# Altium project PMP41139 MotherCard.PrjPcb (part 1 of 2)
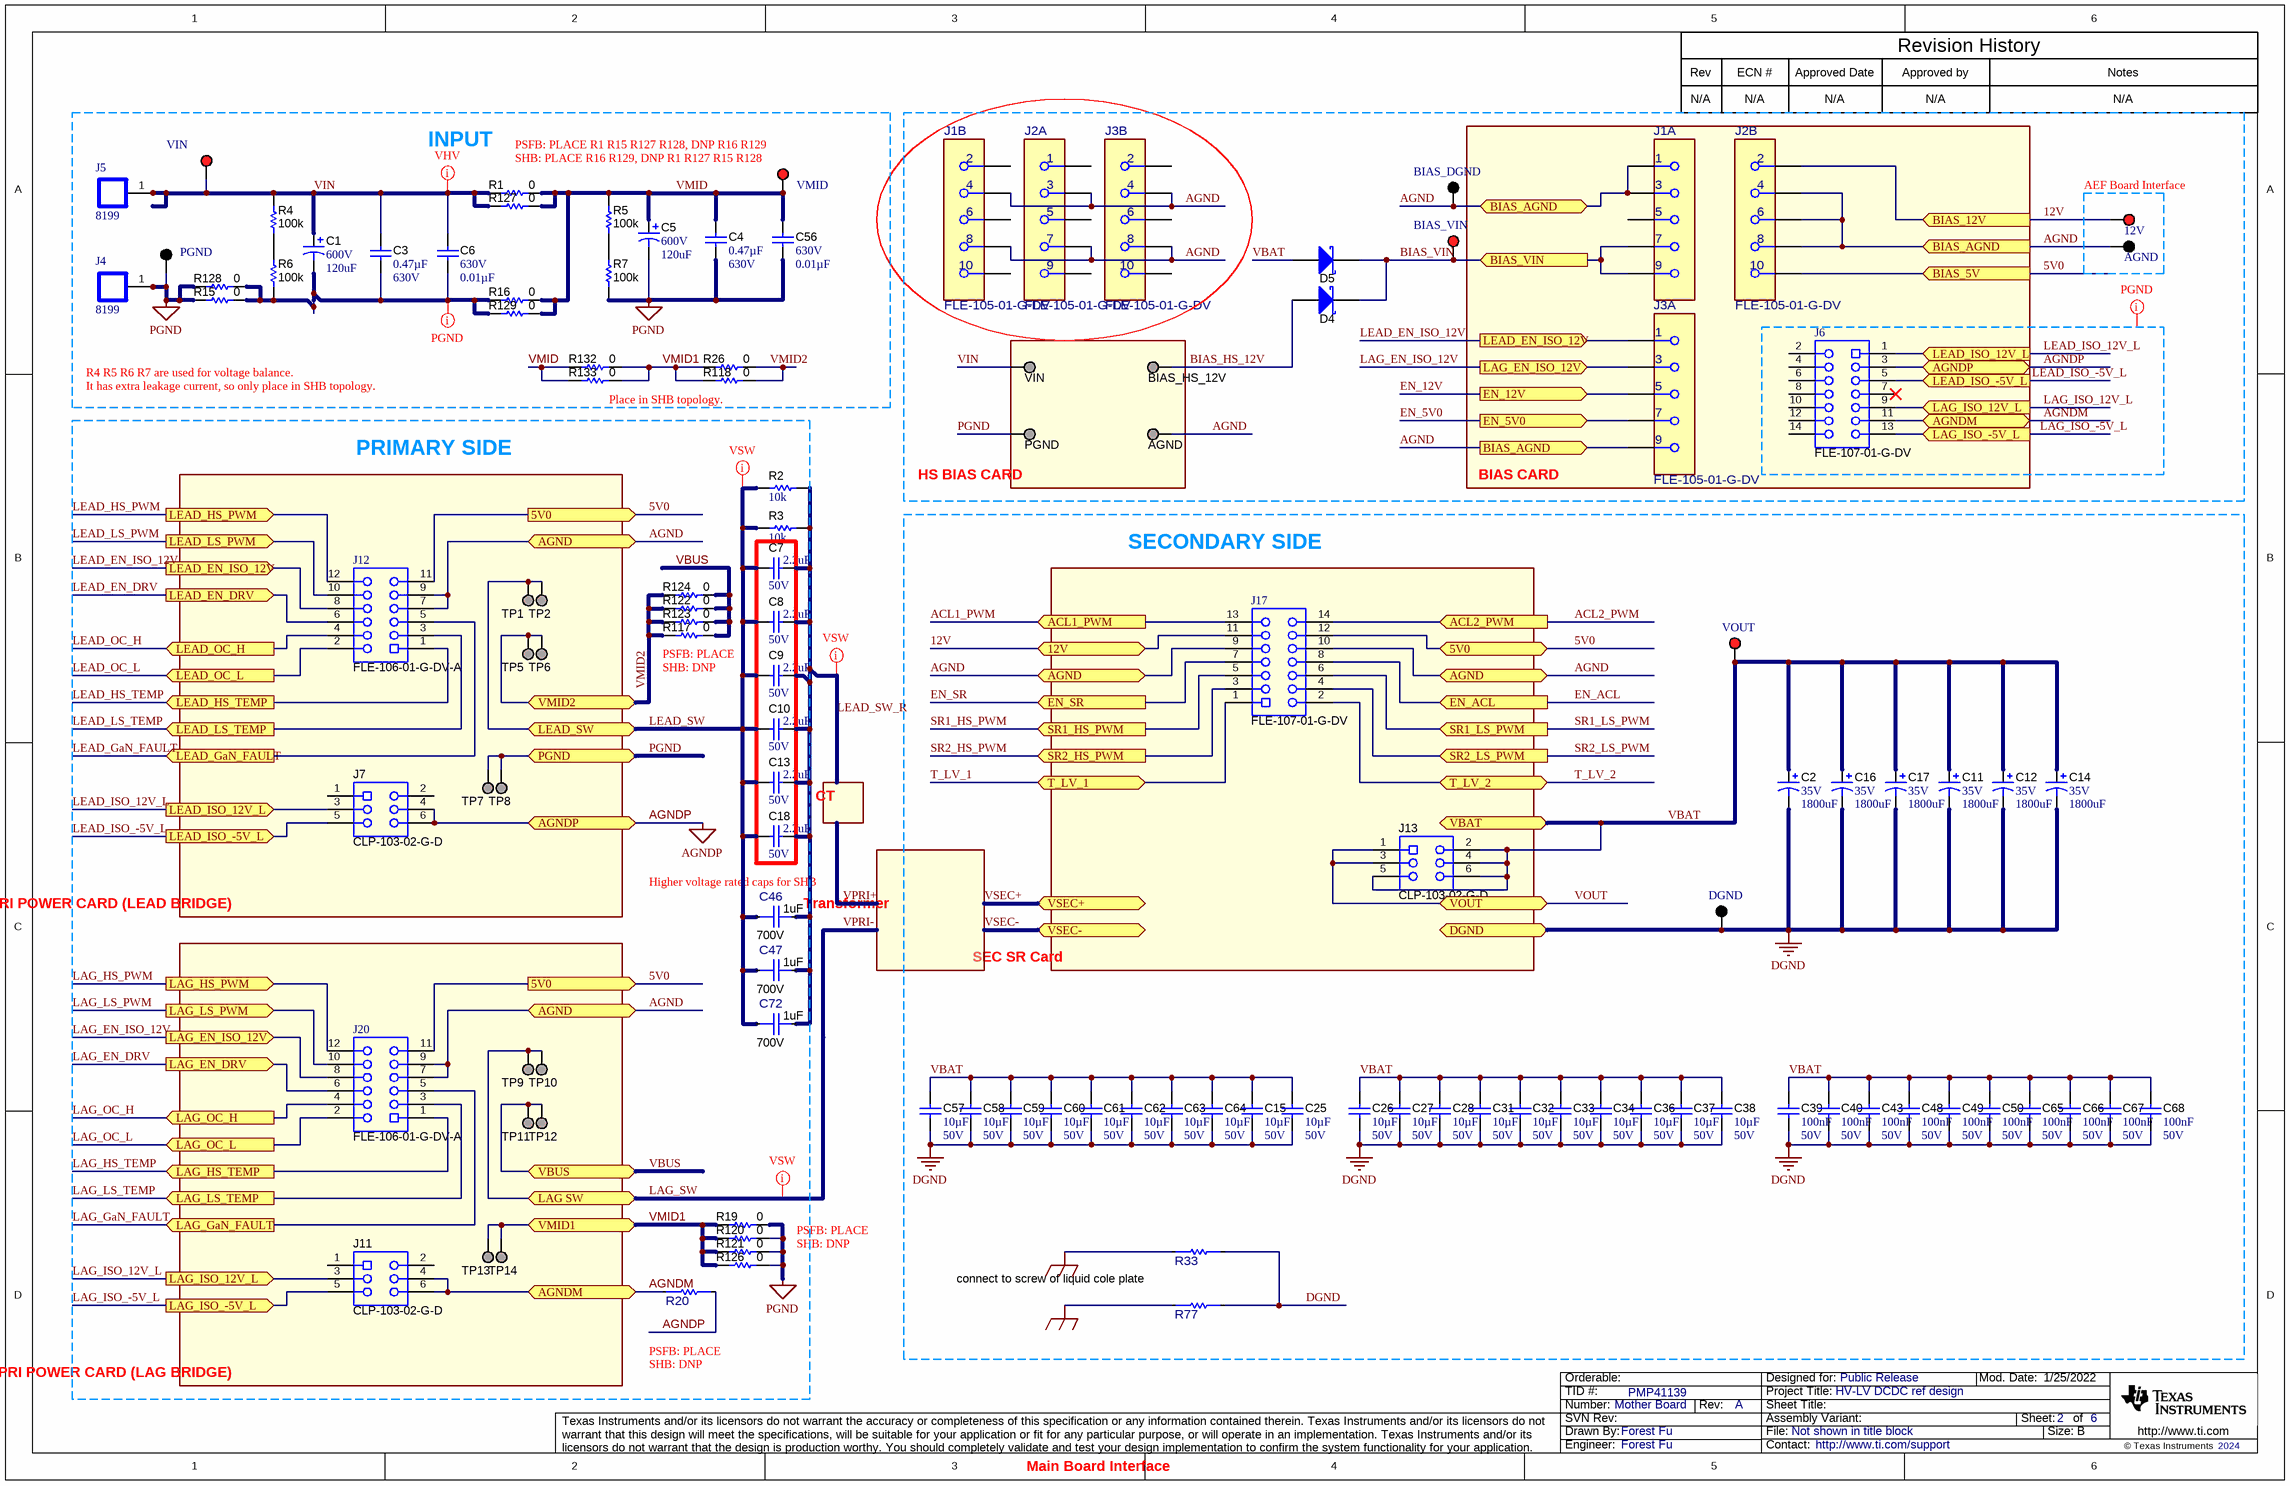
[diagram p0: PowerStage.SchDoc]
CopyrightYear: 2024; PCB_Layout: Forest Fu; PCB_Rev: A; PRJ_Customer: Public Release; PRJ_Engineer: Forest Fu; PRJ_Number: Mother Board; PRJ_Title: HV-LV DCDC ref design; SCH_Rev: A; TechSupport: http://www.ti.com/support; TID: PMP41139
6 sheets, 323 parts. Net scope: global (net labels, ports and power ports of the same name join across sheets).
Board file: DCDC MotherCard.PcbDoc
Sheets:
  PowerStage.SchDoc
  Controller.SchDoc
  V Sensor.SchDoc
  I Sensor.SchDoc
  DCDC MotherCard_Hardware.SchDoc
  PowerTree.SchDoc

## Sheet PowerStage.SchDoc
size 431 x 279 mm; Date: Not shown in title block; ApprovedBy: Not shown in title block; CheckedBy: Not shown in title block; Author: Not shown in title block; CompanyName: Not shown in title block; DrawnBy: Forest Fu; Engineer: Not shown in title block; Organization: Not shown in title block; Address1: Not shown in title block; Address2: Not shown in title block; Address3: Not shown in title block; Address4: Not shown in title block; DocumentNumber: 1; Revision: Use project parameter SCH_Rev; SheetNumber: 2; SheetTotal: 6; PageSetup: Record=PageOptions¦CenterHorizontal=True¦CenterVertical=True¦PrintScale=1.00¦XCorrection=1.00¦YCorrection=1.00¦PrintKind=0¦BorderSize=5000000¦LeftOffset=0¦BottomOffset=0¦Orientation=2¦PaperLength=1000¦PaperWidth=1000¦Scale=100¦PaperSource=15¦PrintQuality=600¦MediaType=1¦DitherType=10¦PaperKind=Letter¦PrintScaleMode=1

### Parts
(Parts that share a designator on the sheet are numbered #1, #2 ... from top to bottom, then left to right.)
12V  5000  [Keystone5000]  (value not drawn)
AGND#1  5001  [Keystone5001]  (value not drawn)
AGND#2  0312-0-15-15-34-27-10-0  [Mill-Max_0312-0-15-15-34-27-10-0]  (value not drawn)
BIAS_DGND  5001  [Keystone5001]  (value not drawn)
BIAS_HS_12V  0312-0-15-15-34-27-10-0  [Mill-Max_0312-0-15-15-34-27-10-0]  (value not drawn)
BIAS_VIN  5000  [Keystone5000]  (value not drawn)
C1  VDC_V: 600V  ValueDisplayed: 120uF  [Nichicon_3000x4500_Snap]  (hidden comment: LGN2X121MELB45)
C2  VDC_V: 35V  ValueDisplayed: 1800uF  [B41896_1600x3150]  (hidden comment: B41896C7188M000)
C3  ValueDisplayed: 0.47µF  VDC_V: 630V  [2220_280]  (hidden comment: CGA9P1X7T2J474M250KC)
C4  ValueDisplayed: 0.47µF  VDC_V: 630V  [2220_280]  (hidden comment: CGA9P1X7T2J474M250KC)
C5  VDC_V: 600V  ValueDisplayed: 120uF  [Nichicon_3000x4500_Snap]  (hidden comment: LGN2X121MELB45)
C6  VDC_V: 630V  ValueDisplayed: 0.01µF  [1210_150]  (hidden comment: CGA6J4C0G2J103J125AA)
C7  VDC_V: 50V  ValueDisplayed: 2.2uF  [1206_180]  (hidden comment: CGA5L3X7R1H225K160AB)
C8  VDC_V: 50V  ValueDisplayed: 2.2uF  [1206_180]  (hidden comment: CGA5L3X7R1H225K160AB)
C9  VDC_V: 50V  ValueDisplayed: 2.2uF  [1206_180]  (hidden comment: CGA5L3X7R1H225K160AB)
C10  VDC_V: 50V  ValueDisplayed: 2.2uF  [1206_180]  (hidden comment: CGA5L3X7R1H225K160AB)
C11  VDC_V: 35V  ValueDisplayed: 1800uF  [B41896_1600x3150]  (hidden comment: B41896C7188M000)
C12  VDC_V: 35V  ValueDisplayed: 1800uF  [B41896_1600x3150]  (hidden comment: B41896C7188M000)
C13  VDC_V: 50V  ValueDisplayed: 2.2uF  [1206_180]  (hidden comment: CGA5L3X7R1H225K160AB)
C14  VDC_V: 35V  ValueDisplayed: 1800uF  [B41896_1600x3150]  (hidden comment: B41896C7188M000)
C15  ValueDisplayed: 10µF  VDC_V: 50V  [1210_280]  (hidden comment: CGA6P3X7S1H106K250AE)
C16  VDC_V: 35V  ValueDisplayed: 1800uF  [B41896_1600x3150]  (hidden comment: B41896C7188M000)
C17  VDC_V: 35V  ValueDisplayed: 1800uF  [B41896_1600x3150]  (hidden comment: B41896C7188M000)
C18  VDC_V: 50V  ValueDisplayed: 2.2uF  [1206_180]  (hidden comment: CGA5L3X7R1H225K160AB)
C25  ValueDisplayed: 10µF  VDC_V: 50V  [1210_280]  (hidden comment: CGA6P3X7S1H106K250AE)
C26  ValueDisplayed: 10µF  VDC_V: 50V  [1210_280]  (hidden comment: CGA6P3X7S1H106K250AE)
C27  ValueDisplayed: 10µF  VDC_V: 50V  [1210_280]  (hidden comment: CGA6P3X7S1H106K250AE)
C28  ValueDisplayed: 10µF  VDC_V: 50V  [1210_280]  (hidden comment: CGA6P3X7S1H106K250AE)
C31  ValueDisplayed: 10µF  VDC_V: 50V  [1210_280]  (hidden comment: CGA6P3X7S1H106K250AE)
C32  ValueDisplayed: 10µF  VDC_V: 50V  [1210_280]  (hidden comment: CGA6P3X7S1H106K250AE)
C33  ValueDisplayed: 10µF  VDC_V: 50V  [1210_280]  (hidden comment: CGA6P3X7S1H106K250AE)
C34  ValueDisplayed: 10µF  VDC_V: 50V  [1210_280]  (hidden comment: CGA6P3X7S1H106K250AE)
C36  ValueDisplayed: 10µF  VDC_V: 50V  [1210_280]  (hidden comment: CGA6P3X7S1H106K250AE)
C37  ValueDisplayed: 10µF  VDC_V: 50V  [1210_280]  (hidden comment: CGA6P3X7S1H106K250AE)
C38  ValueDisplayed: 10µF  VDC_V: 50V  [1210_280]  (hidden comment: CGA6P3X7S1H106K250AE)
C39  Cap_F: 100nF  VDC_V: 50V  [0603]  (hidden comment: 06035C104KAZ2A)
C40  Cap_F: 100nF  VDC_V: 50V  [0603]  (hidden comment: 06035C104KAZ2A)
C43  Cap_F: 100nF  VDC_V: 50V  [0603]  (hidden comment: 06035C104KAZ2A)
C46  ValueDisplayed: 1uF  VDC_V: 700V  [FP-B58035U7105M052_SMD2-MFG]  (hidden comment: B58035U7105M052)
C47  ValueDisplayed: 1uF  VDC_V: 700V  [FP-B58035U7105M052_SMD2-MFG]  (hidden comment: B58035U7105M052)
C48  Cap_F: 100nF  VDC_V: 50V  [0603]  (hidden comment: 06035C104KAZ2A)
C49  Cap_F: 100nF  VDC_V: 50V  [0603]  (hidden comment: 06035C104KAZ2A)
C50  Cap_F: 100nF  VDC_V: 50V  [0603]  (hidden comment: 06035C104KAZ2A)
C56  VDC_V: 630V  ValueDisplayed: 0.01µF  [1210_150]  (hidden comment: CGA6J4C0G2J103J125AA)
C57  ValueDisplayed: 10µF  VDC_V: 50V  [1210_280]  (hidden comment: CGA6P3X7S1H106K250AE)
C58  ValueDisplayed: 10µF  VDC_V: 50V  [1210_280]  (hidden comment: CGA6P3X7S1H106K250AE)
C59  ValueDisplayed: 10µF  VDC_V: 50V  [1210_280]  (hidden comment: CGA6P3X7S1H106K250AE)
C60  ValueDisplayed: 10µF  VDC_V: 50V  [1210_280]  (hidden comment: CGA6P3X7S1H106K250AE)
C61  ValueDisplayed: 10µF  VDC_V: 50V  [1210_280]  (hidden comment: CGA6P3X7S1H106K250AE)
C62  ValueDisplayed: 10µF  VDC_V: 50V  [1210_280]  (hidden comment: CGA6P3X7S1H106K250AE)
C63  ValueDisplayed: 10µF  VDC_V: 50V  [1210_280]  (hidden comment: CGA6P3X7S1H106K250AE)
C64  ValueDisplayed: 10µF  VDC_V: 50V  [1210_280]  (hidden comment: CGA6P3X7S1H106K250AE)
C65  Cap_F: 100nF  VDC_V: 50V  [0603]  (hidden comment: 06035C104KAZ2A)
C66  Cap_F: 100nF  VDC_V: 50V  [0603]  (hidden comment: 06035C104KAZ2A)
C67  Cap_F: 100nF  VDC_V: 50V  [0603]  (hidden comment: 06035C104KAZ2A)
C68  Cap_F: 100nF  VDC_V: 50V  [0603]  (hidden comment: 06035C104KAZ2A)
C72  ValueDisplayed: 1uF  VDC_V: 700V  [FP-B58035U7105M052_SMD2-MFG]  (hidden comment: B58035U7105M052)
D4  FSV340AF  [SMAF]  (value not drawn)
D5  FSV340AF  [SMAF]  (value not drawn)
DGND  5001  [Keystone5001]  (value not drawn)
J1  FLE-105-01-G-DV  [FP-FLE-105-01-G-DV_HDR10-MFG]  (value not drawn)  (parts A,B of 2)
J2  FLE-105-01-G-DV  [FP-FLE-105-01-G-DV_HDR10-MFG]  (parts A,B of 2)
J3  FLE-105-01-G-DV  [FP-FLE-105-01-G-DV_HDR10-MFG]  (parts A,B of 2)
J4  8199  [SCREW_TERMINAL_8199]
J5  8199  [SCREW_TERMINAL_8199]
J6  FLE-107-01-G-DV  [Samtec_FLE-107-01-x-DV]
J7  CLP-103-02-G-D  [Samtec_CLP-103-02-x-D]
J11  CLP-103-02-G-D  [Samtec_CLP-103-02-x-D]
J12  FLE-106-01-G-DV-A  [Samtec_FLE-106-01-x-DV-A]
J13  CLP-103-02-G-D  [Samtec_CLP-103-02-x-D]
J17  FLE-107-01-G-DV  [Samtec_FLE-107-01-x-DV]
J20  FLE-106-01-G-DV-A  [Samtec_FLE-106-01-x-DV-A]
PGND#1  5001  [Keystone5001]  (value not drawn)
PGND#2  0312-0-15-15-34-27-10-0  [Mill-Max_0312-0-15-15-34-27-10-0]  (value not drawn)
R1  ValueDisplayed: 0  [2512]  (hidden comment: RMC1JPTE)
R2  ValueDisplayed: 10k  [1206L]  (hidden comment: CRCW120610K0JNEA)
R3  ValueDisplayed: 10k  [1206L]  (hidden comment: CRCW120610K0JNEA)
R4  ValueDisplayed: 100k  [1206]  (hidden comment: CRCW1206100KJNEA)
R5  ValueDisplayed: 100k  [1206]  (hidden comment: CRCW1206100KJNEA)
R6  ValueDisplayed: 100k  [1206]  (hidden comment: CRCW1206100KJNEA)
R7  ValueDisplayed: 100k  [1206]  (hidden comment: CRCW1206100KJNEA)
R15  ValueDisplayed: 0  [2512]  (hidden comment: RMC1JPTE)
R16  ValueDisplayed: 0  [2512]  (hidden comment: RMC1JPTE)
R19  ValueDisplayed: 0  [2512]  (hidden comment: RMC1JPTE)
R20  RMCF1206ZT0R00  [FP-RMCF1206ZT0R00_1206-MFG]  (value not drawn)
R26  ValueDisplayed: 0  [2512]  (hidden comment: RMC1JPTE)
R33  RMCF1206ZT0R00  [FP-RMCF1206ZT0R00_1206-MFG]  (value not drawn)
R77  RMCF1206ZT0R00  [FP-RMCF1206ZT0R00_1206-MFG]  (value not drawn)
R117  ValueDisplayed: 0  [2512]  (hidden comment: RMC1JPTE)
R118  ValueDisplayed: 0  [2512]  (hidden comment: RMC1JPTE)
R120  ValueDisplayed: 0  [2512]  (hidden comment: RMC1JPTE)
R121  ValueDisplayed: 0  [2512]  (hidden comment: RMC1JPTE)
R122  ValueDisplayed: 0  [2512]  (hidden comment: RMC1JPTE)
R123  ValueDisplayed: 0  [2512]  (hidden comment: RMC1JPTE)
R124  ValueDisplayed: 0  [2512]  (hidden comment: RMC1JPTE)
R126  ValueDisplayed: 0  [2512]  (hidden comment: RMC1JPTE)
R127  ValueDisplayed: 0  [2512]  (hidden comment: RMC1JPTE)
R128  ValueDisplayed: 0  [2512]  (hidden comment: RMC1JPTE)
R129  ValueDisplayed: 0  [2512]  (hidden comment: RMC1JPTE)
R132  ValueDisplayed: 0  [2512]  (hidden comment: RMC1JPTE)
R133  ValueDisplayed: 0  [2512]  (hidden comment: RMC1JPTE)
TP1  0312-0-15-15-34-27-10-0  [Mill-Max_0312-0-15-15-34-27-10-0]  (value not drawn)
TP2  0312-0-15-15-34-27-10-0  [Mill-Max_0312-0-15-15-34-27-10-0]  (value not drawn)
TP5  0312-0-15-15-34-27-10-0  [Mill-Max_0312-0-15-15-34-27-10-0]  (value not drawn)
TP6  0312-0-15-15-34-27-10-0  [Mill-Max_0312-0-15-15-34-27-10-0]  (value not drawn)
TP7  0312-0-15-15-34-27-10-0  [Mill-Max_0312-0-15-15-34-27-10-0]  (value not drawn)
TP8  0312-0-15-15-34-27-10-0  [Mill-Max_0312-0-15-15-34-27-10-0]  (value not drawn)
TP9  0312-0-15-15-34-27-10-0  [Mill-Max_0312-0-15-15-34-27-10-0]  (value not drawn)
TP10  0312-0-15-15-34-27-10-0  [Mill-Max_0312-0-15-15-34-27-10-0]  (value not drawn)
TP11  0312-0-15-15-34-27-10-0  [Mill-Max_0312-0-15-15-34-27-10-0]  (value not drawn)
TP12  0312-0-15-15-34-27-10-0  [Mill-Max_0312-0-15-15-34-27-10-0]  (value not drawn)
TP13  0312-0-15-15-34-27-10-0  [Mill-Max_0312-0-15-15-34-27-10-0]  (value not drawn)
TP14  0312-0-15-15-34-27-10-0  [Mill-Max_0312-0-15-15-34-27-10-0]  (value not drawn)
VIN#1  5000  [Keystone5000]  (value not drawn)
VIN#2  0312-0-15-15-34-27-10-0  [Mill-Max_0312-0-15-15-34-27-10-0]  (value not drawn)
VMID  5000  [Keystone5000]  (value not drawn)
VOUT  5000  [Keystone5000]  (value not drawn)

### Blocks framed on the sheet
BIAS CARD: J1-J3 J6
HS BIAS CARD: AGND#2 BIAS_HS_12V PGND#2 VIN#2
PRI POWER CARD (LEAD BRIDGE): J7 J12 TP1 TP2 TP5-TP8
SEC SR Card: J13 J17
PRI POWER CARD (LAG BRIDGE): J11 J20 TP9-TP14

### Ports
5V0 (bidir), 5V0 (out), 12V (bidir), ACL1_PWM (in), ACL2_PWM (in), AGND (bidir), AGNDM (bidir), AGNDP (bidir), BIAS_5V (in), BIAS_12V (in), BIAS_AGND (bidir), BIAS_AGND (in), BIAS_AGND (out), BIAS_VIN (in), DGND (bidir), EN_5V0 (out), EN_12V (out), EN_ACL (in), EN_SR (in), LAG SW (bidir), LAG_EN_DRV (out), LAG_EN_ISO_12V (out), LAG_GaN_FAULT (in), LAG_HS_PWM (out), LAG_HS_TEMP (in), LAG_ISO_12V_L (in), LAG_ISO_12V_L (out), LAG_ISO_-5V_L (in), LAG_ISO_-5V_L (out), LAG_LS_PWM (out), LAG_LS_TEMP (in), LAG_OC_H (in), LAG_OC_L (in), LEAD_EN_DRV (out), LEAD_EN_ISO_12V (out), LEAD_GaN_FAULT (in), LEAD_HS_PWM (out), LEAD_HS_TEMP (in), LEAD_ISO_12V_L (in), LEAD_ISO_12V_L (out), LEAD_ISO_-5V_L (in), LEAD_ISO_-5V_L (out), LEAD_LS_PWM (out), LEAD_LS_TEMP (in), LEAD_OC_H (in), LEAD_OC_L (in), LEAD_SW (bidir), PGND (bidir), SR1_HS_PWM (in), SR1_LS_PWM (in), SR2_HS_PWM (in), SR2_LS_PWM (in), T_LV_1 (bidir), T_LV_2 (bidir), VBAT (bidir), VBUS (bidir), VMID1 (bidir), VMID2 (bidir), VOUT (bidir), VSEC+ (bidir), VSEC- (bidir)

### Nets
5V0: J2.10 J12.11 J17.12 J20.11 ; port 5V0, port BIAS_5V
AGND: AGND#1.1 AGND#2.1 BIAS_DGND.1 J1.1 J1.3 J1.4 J1.8 J2.3 J2.4 J2.6 J2.7 J2.8 J3.4 J3.8 J3.9 J12.7 J12.9 J17.9 J17.10 J20.7 J20.9 ; port AGND, port BIAS_AGND
AGNDP: J6.3 J7.4 J7.6 R20.2 ; port AGNDP
BIAS_VIN: BIAS_VIN.1 D4.1(K) D5.1(K) J1.7 J1.9 ; port BIAS_VIN
DGND: C2.2(-) C11.2(-) C12.2(-) C14.2(-) C15.2 C16.2(-) C17.2(-) C25.2 C26.2 C27.2 C28.2 C31.2 C32.2 C33.2 C34.2 C36.2 C37.2 C38.2 C39.2 C40.2 C43.2 C48.2 C49.2 C50.2 C57.2 C58.2 C59.2 C60.2 C61.2 C62.2 C63.2 C64.2 C65.2 C66.2 C67.2 C68.2 DGND.1 R33.2 R77.2 ; port DGND
PGND: C4.2 C5.2(-) C56.2 J4.1 J4.2 J4.3 J4.4 J4.5 J4.6 PGND#1.1 PGND#2.1 R7.1 R15.1 R19.2 R120.2 R121.2 R126.2 R128.1 TP7.1 TP8.1 ; port PGND
SHIELD_GND1: R33.1
SHIELD_GND2: R77.1
12V: 12V.1 J2.2 J17.11 ; port BIAS_12V, port 12V
ACL1_PWM: J17.13 ; port ACL1_PWM
ACL2_PWM: J17.14 ; port ACL2_PWM
AGNDM: J6.11 J11.4 J11.6 R20.1 ; port AGNDM
BIAS_HS_12V: BIAS_HS_12V.1 D4.2(A)
EN_5V0: J3.7 ; port EN_5V0
EN_12V: J3.5 ; port EN_12V
EN_ACL: J17.8 ; port EN_ACL
EN_SR: J17.7 ; port EN_SR
LAG_EN_DRV: J20.6 ; port LAG_EN_DRV
LAG_EN_ISO_12V: J3.3 J20.8 ; port LAG_EN_ISO_12V
LAG_GaN_FAULT: J20.5 ; port LAG_GaN_FAULT
LAG_HS_PWM: J20.12 ; port LAG_HS_PWM
LAG_HS_TEMP: J20.1 ; port LAG_HS_TEMP
LAG_ISO_12V_L: J6.9 J11.3 ; port LAG_ISO_12V_L
LAG_ISO_-5V_L: J6.13 J11.5 ; port LAG_ISO_-5V_L
LAG_LS_PWM: J20.10 ; port LAG_LS_PWM
LAG_LS_TEMP: J20.3 ; port LAG_LS_TEMP
LAG_OC_H: J20.4 ; port LAG_OC_H
LAG_OC_L: J20.2 ; port LAG_OC_L
LAG_SW: TP9.1 TP10.1 ; port LAG SW  [also labelled VPRI-]
LEAD_EN_DRV: J12.6 ; port LEAD_EN_DRV
LEAD_EN_ISO_12V: J3.1 J12.8 ; port LEAD_EN_ISO_12V
LEAD_GaN_FAULT: J12.5 ; port LEAD_GaN_FAULT
LEAD_HS_PWM: J12.12 ; port LEAD_HS_PWM
LEAD_HS_TEMP: J12.1 ; port LEAD_HS_TEMP
LEAD_ISO_12V_L: J6.1 J7.3 ; port LEAD_ISO_12V_L
LEAD_ISO_-5V_L: J6.5 J7.5 ; port LEAD_ISO_-5V_L
LEAD_LS_PWM: J12.10 ; port LEAD_LS_PWM
LEAD_LS_TEMP: J12.3 ; port LEAD_LS_TEMP
LEAD_OC_H: J12.4 ; port LEAD_OC_H
LEAD_OC_L: J12.2 ; port LEAD_OC_L
LEAD_SW: C7.2 C8.2 C9.2 C10.2 C13.2 C18.2 C46.1 C47.1 C72.1 R2.1 R3.1 TP1.1 TP2.1 ; port LEAD_SW
LEAD_SW_R: C7.1 C8.1 C9.1 C10.1 C13.1 C18.1 C46.2 C47.2 C72.2 R2.2 R3.2
SR1_HS_PWM: J17.5 ; port SR1_HS_PWM
SR1_LS_PWM: J17.6 ; port SR1_LS_PWM
SR2_HS_PWM: J17.3 ; port SR2_HS_PWM
SR2_LS_PWM: J17.4 ; port SR2_LS_PWM
T_LV_1: J17.1 ; port T_LV_1
T_LV_2: J17.2 ; port T_LV_2
VBAT: C2.1(+) C11.1(+) C12.1(+) C14.1(+) C15.1 C16.1(+) C17.1(+) C25.1 C26.1 C27.1 C28.1 C31.1 C32.1 C33.1 C34.1 C36.1 C37.1 C38.1 C39.1 C40.1 C43.1 C48.1 C49.1 C50.1 C57.1 C58.1 C59.1 C60.1 C61.1 C62.1 C63.1 C64.1 C65.1 C66.1 C67.1 C68.1 D5.2(A) J13.2 J13.4 J13.5 J13.6 VOUT.1 ; port VBAT
VBUS: R117.2 R122.2 R123.2 R124.2 TP11.1 TP12.1 ; port VBUS
VIN: C1.1(+) C3.1 C6.1 J5.1 J5.2 J5.3 J5.4 J5.5 J5.6 R1.1 R4.2 R127.1 VIN#1.1 VIN#2.1
VMID: C4.1 C5.1(+) C56.1 R1.2 R5.2 R16.2 R127.2 R129.2 R132.1 R133.1 VMID.1
VMID1: R19.1 R26.1 R118.1 R120.1 R121.1 R126.1 R132.2 R133.2 TP13.1 TP14.1 ; port VMID1
VMID2: R26.2 R117.1 R118.2 R122.1 R123.1 R124.1 TP5.1 TP6.1 ; port VMID2
VOUT: J13.1 J13.3 ; port VOUT
NetC1_2: C1.2(-) C3.2 C6.2 R6.1 R15.2 R16.1 R128.2 R129.1
NetR4_1: R4.1 R6.2
NetR5_1: R5.1 R7.2

Not connected (* = marked no-connect by the designer): J1 2 5 6 10; J2 1 5 9; J3 2 6 10; J6 2 4 6 7* 8 10 12 14; J7 1 2; J11 1 2

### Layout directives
net class VHV: VIN
net class PGND: AGNDM, AGNDP, LAG_ISO_12V_L, LAG_ISO_-5V_L, LEAD_ISO_12V_L, LEAD_ISO_-5V_L, NetC1_2
net class VSW: LAG_SW, LEAD_SW, LEAD_SW_R

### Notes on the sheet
- Rev
- N/A
- ECN #
- Approved Date
- Approved by
- Revision History
- Notes
- INPUT
- PSFB: PLACE R1 R15 R127 R128, DNP R16 R129
- SHB: PLACE R16 R129, DNP R1 R127 R15 R128
- (near 12V) AEF Board Interface
- It has extra leakage current, so only place in SHB topology.
- R4 R5 R6 R7 are used for voltage balance.
- Place in SHB topology.
- PRIMARY SIDE
- SECONDARY SIDE
- (near R117) PSFB: PLACE
- SHB: DNP
- CT
- Higher voltage rated caps for SHB
- Transformer
- PSFB: PLACE
- connect to screw of liquid cole plate
- Main Board Interface

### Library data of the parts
12V BIAS_VIN VIN#1 VMID VOUT = CMP-0055137-2: Test Point, Miniature, Red, TH; Manufacturer: Keystone Electronics; Green_REACh: Passed; Green_Lifecycle: Active; ContactFinish: Silver; CNHeader: FALSE; CT: TRUE
AGND#1 BIAS_DGND DGND PGND#1 = CMP-0055138-2: Test Point, Miniature, Black, TH; Manufacturer: Keystone Electronics; ContactFinish: Silver; CNHeader: FALSE; Green_Lifecycle: Active; Green_REACh: Passed; CT: TRUE
AGND#2 BIAS_HS_12V PGND#2 TP1 TP2 TP5-TP14 VIN#2 = CMP-0055026-1: Pin Receptacle, .032-.046" .075" Dia, Gold, TH; Manufacturer: Mill-Max; CNHeader: FALSE; Green_Lifecycle: Active; Gender: Female; Green_REACh: Passed
C1 C5 = CMP-0010058-3: CAP, AL, 120 uF, 600 V, +/- 20%, TH; Manufacturer: Nichicon; TaMin_C: -25°C; Polarized: Y; SizeAreaWB_mm2: 1024; Value1: Unknown; U/M: EA; Value: 120uF; TaMax_C: 105°C; SizeZ_mm: 47; SizeX_mm: 30; Cap_Case: 30x45mm; SizeArea_mm2: 900; CompType: Capacitor; AEC Qualified: N; Cap_F: 120µF; IRMS_A: 7.4dA; AEC Category: Q200
C2 C11 C12 C14 C16 C17 = CMP-0010311-2: CAP, AL, 1800 uF, 35 V, +/- 20%, 0.023 ohm, AEC-Q200 Grade 1, TH; Manufacturer: TDK; TaMin_C: -55°C; ESR_ohm: 0.023; Polarized: Y; SizeAreaWB_mm2: 324; U/M: EA; Value: 1800uF; TaMax_C: 125°C; SizeZ_mm: 33.5; SizeX_mm: 16; Cap_Case: 16x31.5mm; SizeArea_mm2: 256; CompType: Capacitor; Cap_F: 1.8mF; IRMS_A: 3.16A; AEC Grade: 1; AEC Category: Q200
C3 C4 = CMP-0860865-1: CAP, CERM, 0.47 µF, 630 V,+/- 20%, X7T, AEC-Q200 Grade 1, 2220; Manufacturer: TDK; SizeZ_mm: 2.8; SizeY_mm: 5; AEC Qualified: Y; Cap_Case: 2220; Polarized: N; SizeArea_mm2: 28.5; U/M: EA; AEC Grade: 1; AEC Category: Q200; TaMax_C: 125°C; TaMin_C: -55°C; Cap_F: 470nF; SizeAreaWB_mm2: 53.9; SizeX_mm: 5.7; Value: 0.47uF
C6 C56 = CMP-0860380-1: CAP, CERM, 0.01 µF, 630 V,+/- 5%, C0G/NP0, AEC-Q200 Grade 1, 1210; Manufacturer: TDK; AEC Qualified: Y; Polarized: N; SizeZ_mm: 1.5; SizeArea_mm2: 8; U/M: EA; SizeX_mm: 3.2; SizeY_mm: 2.5; Cap_F: 10nF; SizeAreaWB_mm2: 14.7; TaMin_C: -55°C; Cap_Case: 1210; Value: 0.01uF; AEC Grade: 1; TaMax_C: 125°C; AEC Category: Q200
C7-C10 C13 C18 = CMP-0008788-2: CAP, CERM, 2.2 uF, 50 V, +/- 10%, X7R, AEC-Q200 Grade 1, 1206; Manufacturer: TDK; TaMin_C: -55°C; ESR_ohm: 5.887m; Polarized: N; SizeAreaWB_mm2: 10.92; Value1: 0.005887 ohm; U/M: EA; Value: 2.2uF; TaMax_C: 125°C; SizeZ_mm: 1.8; SizeX_mm: 3.2; SizeY_mm: 1.6; SizeArea_mm2: 5.12; AEC Qualified: Y; Cap_F: 2.2µF; IRMS_A: 2.99226A; AEC Grade: 1; AEC Category: Q200
C15 C25-C28 C31-C34 C36-C38 C57-C64 = CMP-0085350-1: CAP, CERM, 10 µF, 50 V,+/- 10%, X7S, AEC-Q200 Grade 1, 1210; Manufacturer: TDK; SizeZ_mm: 2.8; SizeY_mm: 2.5; SizeAreaWB_mm2: 14.7; AEC Qualified: Y; SizeArea_mm2: 8; U/M: EA; Value: 10uF; Polarized: N; TaMax_C: 125°C; SizeX_mm: 3.2; Cap_Case: 1210; TaMin_C: -55°C; AEC Grade: 1; AEC Category: Q200
C39 C40 C43 C48-C50 C65-C68 = CMP-0079095-1: CAP, CERM, 0.1 µF, 50 V,+/- 10%, X7R, AEC-Q200 Grade 1, 0603; Manufacturer: AVX; SizeAreaWB_mm2: 4.68; SizeArea_mm2: 1.28; AEC Qualified: Y; AEC Category: Q200; Value: 0.1uF; TaMax_C: 125°C; SizeZ_mm: 1; Polarized: N; TaMin_C: -55°C; SizeY_mm: 0.8; U/M: EA; SizeX_mm: 1.6; ValueDisplayed: 0.1µF
C46 C47 C72 = CMP-0124726-1: 1 µF ±20% 700V Ceramic Capacitor Stacked SMD, 4 J-Lead; Manufacturer: TDK; AEC Grade: Grade 0; AEC Qualified: Yes; Cap_F: 1µF; SizeZ_mm: 9.6mm; Value: 1µF
D4 D5 = CMP-0028855-2: Diode, Schottky, 40 V, 3 A, AEC-Q101, SMAF; Manufacturer: Fairchild Semiconductor; Value1: 3A; SizeArea_mm2: 11.75; SizeZ_mm: 1; TJmax_C: 150°C; Vr_V: 40V; SizeX_mm: 4.7; AEC Qualified: Y; SizeY_mm: 2.5; Value2: 0.5V; AEC Category: Q101; Vf_V: 500mV; Value: 40V; Green_REACh: Incomplete; SizeAreaWB_mm2: 19.95; Green_Lifecycle: Not Set
J1-J3 = CMP-0088850-1: 10 Position Receptacle Connector  Surface Mount; Manufacturer: SAMTEC; ContactFinish: Gold,Nickel; Current_A: 2.9A; Is Female: yes; AEC Qualified: No; Standoff Height: 0.18mm; Conn Orientation: Vertical; Conn Gender: Female; SizeZ_mm: 4.68mm; Row_Count: 2; DUT-Pitch_mm: 1.27mm
J4 J5 = CMP-0055125-1: TERMINAL SCREW PC 30AMP, TH; Manufacturer: Keystone; CNHeader: FALSE; Green_Lifecycle: Active; Green_REACh: Passed; CompType: Screw Connector
J6 J17 = CMP-0075566-1: Receptacle, 1.27mm, 7x2, Gold, SMT; Manufacturer: Samtec; Pitch_mm: 1.27; Gender: Female; CT: True; Row_Count: 2; CompType: Socket Strip; CNHeader: False
J7 J11 J13 = CMP-0055704-1: Receptacle, 1.27mm, 3x2, Gold, SMT; Manufacturer: Samtec; CNHeader: FALSE; Current_A: 3.3A; Gender: Female; Voltage_V: 240V; CompType: Socket Strip; Row_Count: 2; RowSpacing_mm: 1.27; CT: TRUE; Cert_UL: Y
J12 J20 = CMP-0075577-1: Receptacle, 1.27mm, 6x2, Gold, SMT; Manufacturer: Samtec; Pitch_mm: 1.27; Gender: Female; Cert_CSA: Y; Current_A: 2A; CT: True; Row_Count: 2; CompType: Socket Strip; CNHeader: False
R1 R15 R16 R19 R26 R117 R118 R120-R124 R126-R129 R132 R133 = CMP-0080698-1: RES, 0, 0%, 1 W, AEC-Q200 Grade 0, 2512; Manufacturer: Kamaya; SizeAreaWB_mm2: 43.16; SizeArea_mm2: 20.16; AEC Qualified: Y; AEC Category: Q200; Value: 0; SizeZ_mm: 0.71; SizeY_mm: 3.2; Power_W: 1W; SizeX_mm: 6.3
R2 R3 = CMP-0018576-3: RES, 10 k, 5%, 0.25 W, AEC-Q200 Grade 0, 1206; Manufacturer: Vishay-Dale; Power_W: 250mW; TempCo: 200 ppm/C; Value_Code: 10k0; Value: 10k; EIA_Code: E24; SizeX_mm: 3.2; SizeY_mm: 1.6; SizeZ_mm: 1.35; Value2: 0.25W; SizeArea_mm2: 5.12; AEC Qualified: Y; VDC_V: 200V; AEC Category: Q200; AEC Grade: 0
R4-R7 = CMP-0018574-3: RES, 100 k, 5%, 0.25 W, AEC-Q200 Grade 0, 1206; Manufacturer: Vishay-Dale; Power_W: 250mW; TempCo: 200 ppm/C; Value: 100k; EIA_Code: E24; SizeX_mm: 3.2; SizeY_mm: 1.6; SizeZ_mm: 1.35; Value2: 0.25W; SizeArea_mm2: 5.12; AEC Qualified: Y; VDC_V: 200V; AEC Category: Q200; AEC Grade: 0
R20 R33 R77 = CMP-0093609-1: 0Ω ±0 0.25W 1206 Thick Film Chip Resistor AEC-Q200 compliant; Manufacturer: Stackpole Electronics; Res_ohm: 0; AEC Qualified: Yes; Value: 0; VDC_V: 200V; AEC Grade: Grade 0; Power_W: 250mW; SizeZ_mm: 0.7mm

## Sheet Controller.SchDoc
size 431 x 279 mm; Date: Not shown in title block; ApprovedBy: Not shown in title block; CheckedBy: Not shown in title block; Author: Not shown in title block; CompanyName: Not shown in title block; DrawnBy: Forest Fu; Engineer: Not shown in title block; Organization: Not shown in title block; Address1: Not shown in title block; Address2: Not shown in title block; Address3: Not shown in title block; Address4: Not shown in title block; DocumentNumber: 1; Revision: Use project parameter SCH_Rev; SheetNumber: 3; SheetTotal: 6; PageSetup: Record=PageOptions¦CenterHorizontal=True¦CenterVertical=True¦PrintScale=1.00¦XCorrection=1.00¦YCorrection=1.00¦PrintKind=0¦BorderSize=5000000¦LeftOffset=0¦BottomOffset=0¦Orientation=2¦PaperLength=1000¦PaperWidth=1000¦Scale=100¦PaperSource=15¦PrintQuality=600¦MediaType=1¦DitherType=10¦PaperKind=Letter¦PrintScaleMode=1
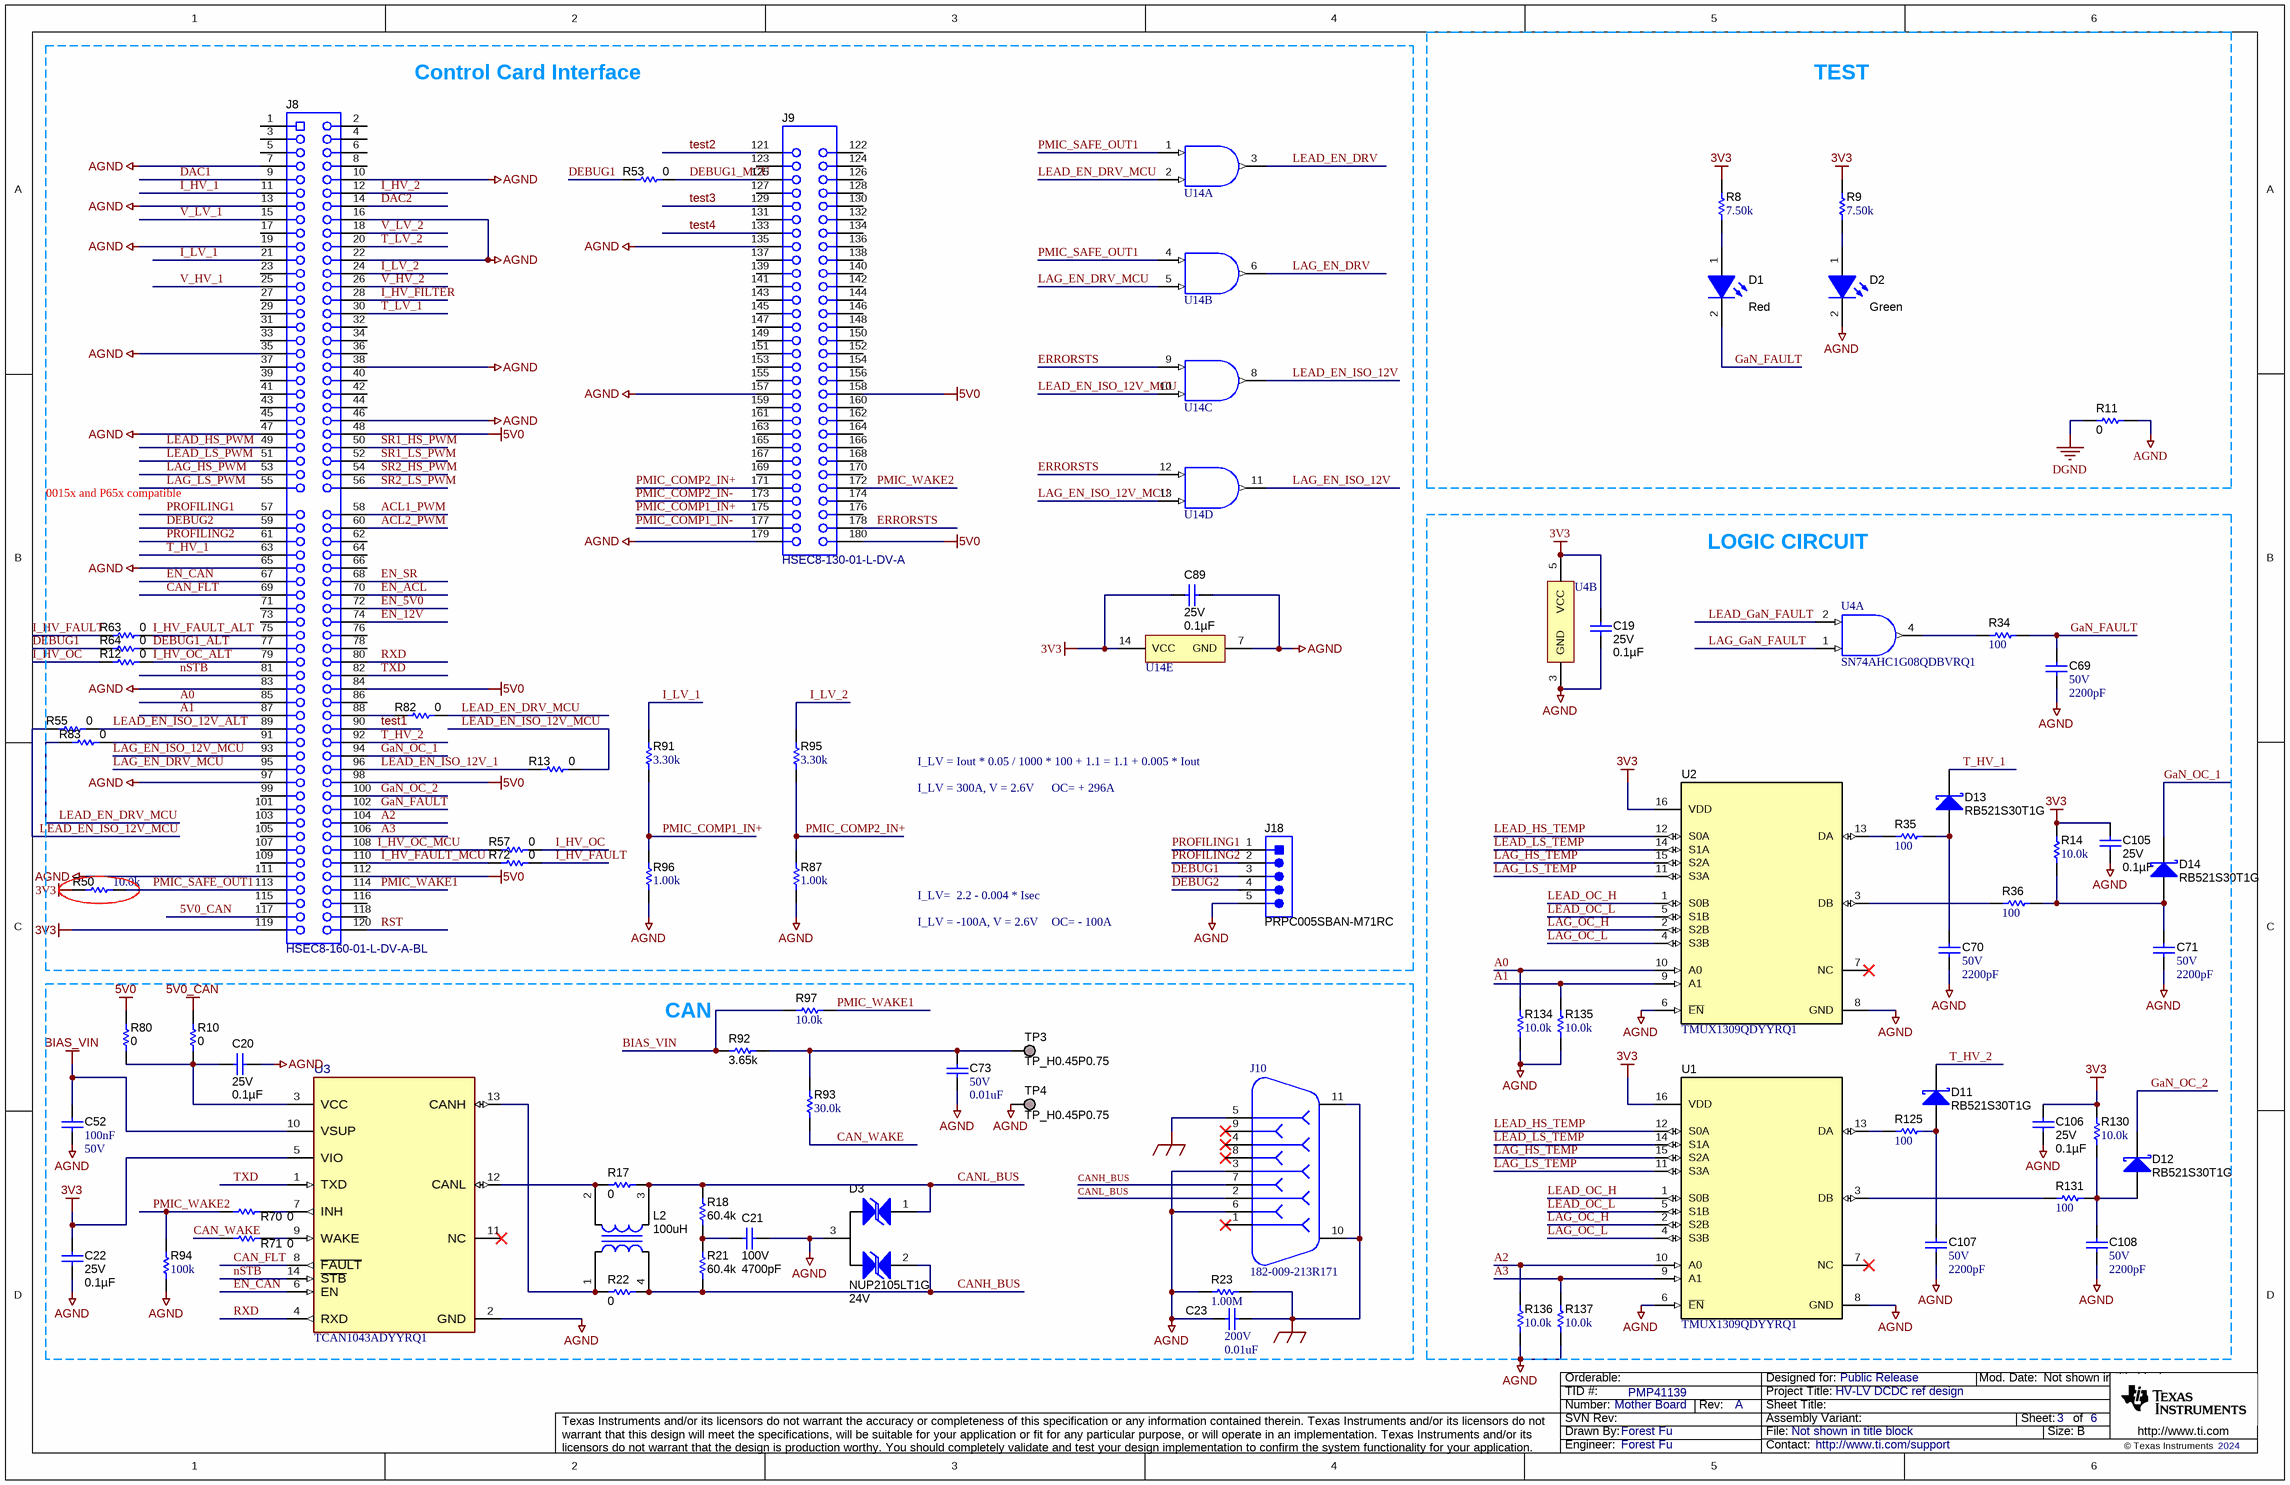
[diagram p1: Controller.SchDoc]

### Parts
C19  VDC_V: 25V  ValueDisplayed: 0.1µF  [0402]  (hidden comment: CGA2B3X7R1E104K050BB)
C20  VDC_V: 25V  ValueDisplayed: 0.1µF  [0402]  (hidden comment: CGA2B3X7R1E104K050BB)
C21  VDC_V: 100V  ValueDisplayed: 4700pF  [0603]  (hidden comment: CGA3E2X7R2A472K080AA)
C22  VDC_V: 25V  ValueDisplayed: 0.1µF  [0402]  (hidden comment: CGA2B3X7R1E104K050BB)
C23  VDC_V: 200V  ValueDisplayed: 0.01uF  [1206]  (hidden comment: C1206C103J2GACAUTO)
C52  Cap_F: 100nF  VDC_V: 50V  [0603]  (hidden comment: 06035C104KAZ2A)
C69  VDC_V: 50V  ValueDisplayed: 2200pF  [0402]  (hidden comment: GCM155R71H222KA37D)
C70  VDC_V: 50V  ValueDisplayed: 2200pF  [0402]  (hidden comment: GCM155R71H222KA37D)
C71  VDC_V: 50V  ValueDisplayed: 2200pF  [0402]  (hidden comment: GCM155R71H222KA37D)
C73  VDC_V: 50V  ValueDisplayed: 0.01uF  [0402]  (hidden comment: CGA2B3X7R1H103K050BB)
C89  VDC_V: 25V  ValueDisplayed: 0.1µF  [0402]  (hidden comment: CGA2B3X7R1E104K050BB)
C105  VDC_V: 25V  ValueDisplayed: 0.1µF  [0402]  (hidden comment: CGA2B3X7R1E104K050BB)
C106  VDC_V: 25V  ValueDisplayed: 0.1µF  [0402]  (hidden comment: CGA2B3X7R1E104K050BB)
C107  VDC_V: 50V  ValueDisplayed: 2200pF  [0402]  (hidden comment: GCM155R71H222KA37D)
C108  VDC_V: 50V  ValueDisplayed: 2200pF  [0402]  (hidden comment: GCM155R71H222KA37D)
D1  value Red  [LED_LTST-C190_Red]  (hidden comment: LTST-C190CKT)
D2  value Green  [LED_LTST-C190]  (hidden comment: LTST-C190GKT)
D3  NUP2105LT1G  value 24V  [SOT-23]
D11  RB521S30T1G  [SOD-523]
D12  RB521S30T1G  [SOD-523]
D13  RB521S30T1G  [SOD-523]
D14  RB521S30T1G  [SOD-523]
J8  HSEC8-160-01-L-DV-A-BL  [controlCARD-120HSEC]
J9  HSEC8-130-01-L-DV-A  [controlCARD-180HSEC-60pinAddon]
J10  182-009-213R171  [NORCOMP_182-009-213R171]
J18  PRPC005SBAN-M71RC  [Sullins_PRxC005SBAN-M71RC]
L2  ValueDisplayed: 100uH  [ACT45B]  (hidden comment: ACT45B-101-2P-TL003)
R8  ValueDisplayed: 7.50k  [0402]  (hidden comment: ERA-2AEB752X)
R9  ValueDisplayed: 7.50k  [0402]  (hidden comment: ERA-2AEB752X)
R10  ValueDisplayed: 0  [0402]  (hidden comment: CRCW04020000Z0ED)
R11  ValueDisplayed: 0  [0603]  (hidden comment: RMCF0603ZT0R00)
R12  ValueDisplayed: 0  [0402]  (hidden comment: CRCW04020000Z0ED)
R13  ValueDisplayed: 0  [0402]  (hidden comment: CRCW04020000Z0ED)
R14  ValueDisplayed: 10.0k  [0402]  (hidden comment: RK73H1ETTP1002F)
R17  ValueDisplayed: 0  [0603]  (hidden comment: RMCF0603ZT0R00)
R18  ValueDisplayed: 60.4k  [0603]  (hidden comment: CRCW060360K4FKEA)
R21  ValueDisplayed: 60.4k  [0603]  (hidden comment: CRCW060360K4FKEA)
R22  ValueDisplayed: 0  [0603]  (hidden comment: RMCF0603ZT0R00)
R23  ValueDisplayed: 1.00M  [0603]  (hidden comment: CRCW06031M00FKEA)
R34  ValueDisplayed: 100  [0402]  (hidden comment: CRCW0402100RFKED)
R35  ValueDisplayed: 100  [0402]  (hidden comment: CRCW0402100RFKED)
R36  ValueDisplayed: 100  [0402]  (hidden comment: CRCW0402100RFKED)
R50  ValueDisplayed: 10.0k  [0402]  (hidden comment: RK73H1ETTP1002F)
R53  ValueDisplayed: 0  [0402]  (hidden comment: CRCW04020000Z0ED)
R55  ValueDisplayed: 0  [0402]  (hidden comment: CRCW04020000Z0ED)
R57  ValueDisplayed: 0  [0402]  (hidden comment: CRCW04020000Z0ED)
R63  ValueDisplayed: 0  [0402]  (hidden comment: CRCW04020000Z0ED)
R64  ValueDisplayed: 0  [0402]  (hidden comment: CRCW04020000Z0ED)
R70  ValueDisplayed: 0  [0402]  (hidden comment: CRCW04020000Z0ED)
R71  ValueDisplayed: 0  [0402]  (hidden comment: CRCW04020000Z0ED)
R72  ValueDisplayed: 0  [0402]  (hidden comment: CRCW04020000Z0ED)
R80  ValueDisplayed: 0  [0402]  (hidden comment: CRCW04020000Z0ED)
R82  ValueDisplayed: 0  [0402]  (hidden comment: CRCW04020000Z0ED)
R83  ValueDisplayed: 0  [0402]  (hidden comment: CRCW04020000Z0ED)
R87  ValueDisplayed: 1.00k  [0402]  (hidden comment: CRCW04021K00FKED)
R91  ValueDisplayed: 3.30k  [0402]  (hidden comment: RK73H1ETTP3301F)
R92  ValueDisplayed: 3.65k  [0402]  (hidden comment: CRCW04023K65FKED)
R93  ValueDisplayed: 30.0k  [0402]  (hidden comment: CRCW040230K0FKED)
R94  ValueDisplayed: 100k  [0402]  (hidden comment: CRCW0402100KFKED)
R95  ValueDisplayed: 3.30k  [0402]  (hidden comment: RK73H1ETTP3301F)
R96  ValueDisplayed: 1.00k  [0402]  (hidden comment: CRCW04021K00FKED)
R97  ValueDisplayed: 10.0k  [0402]  (hidden comment: RK73H1ETTP1002F)
R125  ValueDisplayed: 100  [0402]  (hidden comment: CRCW0402100RFKED)
R130  ValueDisplayed: 10.0k  [0402]  (hidden comment: RK73H1ETTP1002F)
R131  ValueDisplayed: 100  [0402]  (hidden comment: CRCW0402100RFKED)
R134  ValueDisplayed: 10.0k  [0402]  (hidden comment: RK73H1ETTP1002F)
R135  ValueDisplayed: 10.0k  [0402]  (hidden comment: RK73H1ETTP1002F)
R136  ValueDisplayed: 10.0k  [0402]  (hidden comment: RK73H1ETTP1002F)
R137  ValueDisplayed: 10.0k  [0402]  (hidden comment: RK73H1ETTP1002F)
TP3  TP_H0.45P0.75  [TP_H045P075]  (no BOM)
TP4  TP_H0.45P0.75  [TP_H045P075]  (no BOM)
U1  TMUX1309QDYYRQ1  [DYY0016A]
U2  TMUX1309QDYYRQ1  [DYY0016A]
U3  TCAN1043ADYYRQ1  [DYY0014A-MFG]
U4  SN74AHC1G08QDBVRQ1  [DBV0005A_N]  (parts A,B of 2)
U14  SN74AHC08QPWRG4Q1  [PW0014A_N]  (value not drawn)  (parts A,B,C,D,E of 5)

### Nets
3V3: C19.1 C22.1 C89.1 C105.1 C106.1 J8.119 R8.2 R9.2 R14.2 R50.2 R130.2 U1.16(VDD) U2.16(VDD) U3.5(VIO) U4.5(VCC) U14.14(VCC)
5V0: J8.48 J8.84 J8.98 J8.112 J9.158 J9.180 R80.2
5V0_CAN: J8.117 R10.2
AGND: C19.2 C20.2 C21.2 C22.2 C23.2 C52.2 C69.2 C70.2 C71.2 C73.2 C89.2 C105.2 C106.2 C107.2 C108.2 D2.2(K) D3.3 J8.7 J8.10 J8.13 J8.16 J8.19 J8.22 J8.35 J8.38 J8.46 J8.47 J8.65 J8.83 J8.97 J8.111 J9.135 J9.157 J9.179 J10.3 J10.6 J18.5 R11.2 R23.1 R87.1 R94.1 R96.1 R134.1 R135.1 R136.1 R137.1 TP4.1 U1.6(~{EN}) U1.8(GND) U2.6(~{EN}) U2.8(GND) U3.2(GND) U4.3(GND) U14.7(GND)
BIAS_VIN: C52.1 R92.2 R97.2 U3.10(VSUP)
DGND: R11.1
SHIELD_GND: C23.1 J10.5 J10.10 J10.11 R23.2
A0: J8.85 R134.2 U2.10(A0)
A1: J8.87 R135.2 U2.9(A1)
A2: J8.104 R136.2 U1.10(A0)
A3: J8.106 R137.2 U1.9(A1)
ACL1_PWM: J8.58
ACL2_PWM: J8.60
CAN_FLT: J8.69 U3.8(~{FAULT})
CAN_WAKE: R71.1 R93.1
CANH_BUS: D3.2 J10.7 L2.4 R21.1 R22.2
CANL_BUS: D3.1 J10.2 L2.3 R17.2 R18.2
DAC1: J8.9
DAC2: J8.14
DEBUG1: J18.3 R53.1 R64.1
DEBUG1_ALT: J8.77 R64.2
DEBUG1_MCU: J9.125 R53.2
DEBUG2: J8.59 J18.4
EN_5V0: J8.72
EN_12V: J8.74
EN_ACL: J8.70
EN_CAN: J8.67 U3.6(EN)
EN_SR: J8.68
ERRORSTS: J9.178 U14.9(3A) U14.12(4A)
GaN_FAULT: C69.1 D1.2(K) J8.102 R34.2
GaN_OC_1: D14.1(K) J8.94
GaN_OC_2: D12.1(K) J8.100
I_HV_1: J8.11
I_HV_2: J8.12
I_HV_FAULT: R63.1 R72.2
I_HV_FAULT_ALT: J8.75 R63.2
I_HV_FAULT_MCU: J8.110 R72.1
I_HV_FILTER: J8.28
I_HV_OC: R12.1 R57.2
I_HV_OC_ALT: J8.79 R12.2
I_HV_OC_MCU: J8.108 R57.1
I_LV_1: J8.21 R91.2
I_LV_2: J8.24 R95.2
LAG_EN_DRV: U14.6(2Y)
LAG_EN_DRV_MCU: J8.95 U14.5(2B)
LAG_EN_ISO_12V: U14.11(4Y)
LAG_EN_ISO_12V_MCU: J8.93 U14.13(4B)
LAG_GaN_FAULT: U4.1(A)
LAG_HS_PWM: J8.53
LAG_HS_TEMP: U1.15(S2A) U2.15(S2A)
LAG_LS_PWM: J8.55
LAG_LS_TEMP: U1.11(S3A) U2.11(S3A)
LAG_OC_H: U1.2(S2B) U2.2(S2B)
LAG_OC_L: U1.4(S3B) U2.4(S3B)
LEAD_EN_DRV: U14.3(1Y)
LEAD_EN_DRV_MCU: R82.2 R83.1 U14.2(1B)
LEAD_EN_ISO_12V: U14.8(3Y)
LEAD_EN_ISO_12V_1: J8.96 R13.1
LEAD_EN_ISO_12V_ALT: J8.89 R55.2
LEAD_EN_ISO_12V_MCU: R13.2 R55.1 U14.10(3B)
LEAD_GaN_FAULT: U4.2(B)
LEAD_HS_PWM: J8.49
LEAD_HS_TEMP: U1.12(S0A) U2.12(S0A)
LEAD_LS_PWM: J8.51
LEAD_LS_TEMP: U1.14(S1A) U2.14(S1A)
LEAD_OC_H: U1.1(S0B) U2.1(S0B)
LEAD_OC_L: U1.5(S1B) U2.5(S1B)
nSTB: J8.81 U3.14(~{STB})
PMIC_COMP1_IN+: J9.175 R91.1 R96.2
PMIC_COMP1_IN-: J9.177
PMIC_COMP2_IN+: J9.171 R87.2 R95.1
PMIC_COMP2_IN-: J9.173
PMIC_SAFE_OUT1: J8.113 R50.1 U14.1(1A) U14.4(2A)
PMIC_WAKE1: J8.114 R97.1
PMIC_WAKE2: J9.172 R70.1 R94.2
PROFILING1: J8.57 J18.1
PROFILING2: J8.61 J18.2
RST: J8.120
RXD: J8.80 U3.4(RXD)
SR1_HS_PWM: J8.50
SR1_LS_PWM: J8.52
SR2_HS_PWM: J8.54
SR2_LS_PWM: J8.56
T_HV_1: D13.1(K) J8.63
T_HV_2: D11.1(K) J8.92
T_LV_1: J8.30
T_LV_2: J8.20
test1: J8.90
test2: J9.121
test3: J9.129
test4: J9.133
TXD: J8.82 U3.1(TXD)
V_HV_1: J8.25
V_HV_2: J8.26
V_LV_1: J8.15
V_LV_2: J8.18
NetC20_1: C20.1 R10.1 R80.1 U3.3(VCC)
NetC21_1: C21.1 R18.1 R21.2
NetC70_1: C70.1 D13.2(A) R35.2
NetC71_1: C71.1 D14.2(A) R14.1 R36.2
NetC73_1: C73.1 R92.1 R93.2 TP3.1
NetC107_1: C107.1 D11.2(A) R125.2
NetC108_1: C108.1 D12.2(A) R130.1 R131.2
NetD1_1: D1.1(A) R8.1
NetD2_1: D2.1(A) R9.1
NetJ8_88: J8.88 R82.1
NetJ8_91: J8.91 R83.2
NetL2_1: L2.1 R22.1 U3.13(CANH)
NetL2_2: L2.2 R17.1 U3.12(CANL)
NetR34_1: R34.1 U4.4(Y)
NetR35_1: R35.1 U2.13(DA)
NetR36_1: R36.1 U2.3(DB)
NetR70_2: R70.2 U3.7(INH)
NetR71_2: R71.2 U3.9(WAKE)
NetR125_1: R125.1 U1.13(DA)
NetR131_1: R131.1 U1.3(DB)

Not connected (* = marked no-connect by the designer): J8 1 2 3 4 5 6 8 17 23 27 29 31 32 33 34 36 37 39 40 41 42 43 44 45 62 64 66 71 73 76 78 86 99 101 103 105 107 109 115 116 118; J9 122 123 124 126 127 128 130 131 132 134 136 137 138 139 140 141 142 143 144 145 146 147 148 149 150 151 152 153 154 155 156 159 160 161 162 163 164 165 166 167 168 169 170 174 176; J10 1* 4* 8* 9*; U1 7(NC)*; U2 7(NC)*; U3 11(NC)*

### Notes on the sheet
- Control Card Interface
- TEST
- 0015x and P65x compatible
- LOGIC CIRCUIT
- I_LV = Iout * 0.05 / 1000 * 100 + 1.1 = 1.1 + 0.005 * Iout
- I_LV = 300A, V = 2.6V
- OC= + 296A
- I_LV=  2.2 - 0.004 * Isec
- I_LV = -100A, V = 2.6V
- OC= - 100A
- (near R92) CAN

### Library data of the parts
C19 C20 C22 C89 C105 C106 = CMP-0080610-1: CAP, CERM, 0.1 µF, 25 V,+/- 10%, X7R, AEC-Q200 Grade 1, 0402; Manufacturer: TDK; TaMin_C: -55°C; Polarized: N; SizeAreaWB_mm2: 3; U/M: EA; Value: 0.1uF; TaMax_C: 125°C; SizeZ_mm: 0.6; SizeX_mm: 1; SizeY_mm: 0.5; AEC Qualified: Y; Cap_F: 100nF; AEC Category: Q200
C21 = CMP-0007088-4: CAP, CERM, 4700 pF, 100 V, +/- 10%, X7R, AEC-Q200 Grade 1, 0603; Manufacturer: TDK; TaMin_C: -55°C; ESR_ohm: 4.69862d; Polarized: N; SizeAreaWB_mm2: 4.68; Value1: 0.469862 ohm; U/M: EA; Value: 4700pF; TaMax_C: 125°C; SizeZ_mm: 1; SizeX_mm: 1.6; SizeY_mm: 0.8; SizeArea_mm2: 1.28; AEC Qualified: Y; Cap_F: 4.7nF; IRMS_A: 3.2335dA; AEC Category: Q200
C23 = CMP-0008580-2: CAP, CERM, 0.01 uF, 200 V, +/- 5%, C0G/NP0, AEC-Q200 Grade 1, 1206; Manufacturer: Kemet; TaMin_C: -55°C; Polarized: N; SizeAreaWB_mm2: 10.92; Value1: Unknown; U/M: EA; Value: 0.01uF; TaMax_C: 125°C; SizeZ_mm: 1.35; SizeX_mm: 3.2; SizeY_mm: 1.6; SizeArea_mm2: 5.12; AEC Qualified: Y; Cap_F: 10nF; AEC Grade: 1; AEC Category: Q200
C52 = CMP-0079095-1: as C39 on sheet PowerStage
C69-C71 C107 C108 = CMP-0006357-2: CAP, CERM, 2200 pF, 50 V, +/- 10%, X7R, AEC-Q200 Grade 1, 0402; Manufacturer: MuRata; TaMin_C: -55°C; Polarized: N; SizeAreaWB_mm2: 3; Value1: Unknown; U/M: EA; Value: 2200pF; TaMax_C: 125°C; SizeZ_mm: 0.6; SizeX_mm: 1; SizeY_mm: 0.5; AEC Qualified: Y; Cap_F: 2.2nF; AEC Category: Q200
C73 = CMP-0006324-2: CAP, CERM, 0.01 uF, 50 V, +/- 10%, X7R, AEC-Q200 Grade 1, 0402; Manufacturer: TDK; TaMin_C: -55°C; ESR_ohm: 3.33065d; Polarized: N; SizeAreaWB_mm2: 3; Value1: 0.333065 ohm; U/M: EA; Value: 0.01uF; TaMax_C: 125°C; SizeZ_mm: 0.6; SizeX_mm: 1; SizeY_mm: 0.5; AEC Qualified: Y; Cap_F: 10nF; IRMS_A: 3.23373dA; AEC Category: Q200
D1 = CMP-0002842-2: LED, Red, SMD; Manufacturer: Lite-On; Power_TotalModule: 62.5mW; Value1: 0.0625W; Io_A: 20mA; Value2: 2V; Tjmax_C: 85°C
D2 = CMP-0002827-3: LED, Green, SMD; Manufacturer: Lite-On; Power_TotalModule: 100mW; Value2: 2.1V; Io_A: 20mA; Value1: 0.1W
D3 = CMP-0005919-2: Diode, TVS, Bi, 24 V, SOT-23; Manufacturer: ON Semiconductor; Power_W: 350mW; SizeAreaWB_mm2: 14; Value1: 0.35W; U/M: EA; SizeZ_mm: 1.1; SizeX_mm: 2.5; SizeY_mm: 3; SizeArea_mm2: 7.5; AEC Category: Q101
D11-D14 = CMP-0028768-3: Diode, Schottky, 30 V, 0.2 A, AEC-Q101, SOD-523; Manufacturer: ON Semiconductor; SizeArea_mm2: 1.53; Vr_V: 30V; Green_Lifecycle: Not Set; Value2: 0.5V; Value1: 0.2A; AEC Qualified: Y; SizeY_mm: 0.9; AEC Category: Q101; SizeZ_mm: 0.65; Vf_V: 500mV; Io_A: 200mA; Green_REACh: Incomplete; SizeAreaWB_mm2: 5.13; TJmax_C: 125°C; Value: 30V; SizeX_mm: 1.7
J8 = CMP-0003814-2: C2000 controlCARD-120HSEC connector, SMT; Manufacturer: Samtec; Note: The pin numbering does not match Samtec datasheet
J9 = CMP-0003859-2: C2000 controlCARD-180HSEC (60-pin addon) connector, SMT; Manufacturer: Samtec; Note: The pin numbering does not match Samtec datasheet
J10 = CMP-0074955-1: CONN DB9 FEMALE R/A SOLDER TH; Manufacturer: NorComp; CNHeader: False; Green_Lifecycle: Not Set; Green_REACh: Incomplete; CompType: Connector
J18 = CMP-0054624-1: Header, 2.54mm, 5x1, Gold, R/A, TH; Manufacturer: Sullins Connector Solutions; CNHeader: TRUE; Current_A: 3A; Shrouded: N; Gender: Male; Row_Count: 1; Pitch_mm: 2.54; CT: FALSE; Cert_UL: Y
L2 = CMP-0062430-2: Inductor, Ferrite, 100 uH, 0.15 A, 2 ohm, SMD; Manufacturer: TDK; Isat: 0.15A @ % inductance drop; Green_Lifecycle: Active; SizeAreaWB_mm2: 23.1; DCR_ohm: 2; Green_REACh: Passed; Value1: 2 ohm; Value: 100uH; Imax_A: 1.5dA; SizeZ_mm: 3; SizeX_mm: 4.5; SizeY_mm: 3.2; Value2: 0.15A; SizeArea_mm2: 14.4; Ind_H: 100µH; AEC Category: Q200
R8 R9 = CMP-0026786-1: RES, 7.50 k, 0.1%, 0.063 W, AEC-Q200 Grade 0, 0402; Manufacturer: Panasonic; Power_W: 63mW; TempCo: 25 ppm/C; Value_Code: 7k50; U/M: EA; Value: 7.50k; EIA_Code: E192; Res_ohm: 7.5k; SizeX_mm: 1; SizeY_mm: 0.5; SizeZ_mm: 0.6; Value2: 0.063W; AEC Qualified: Y; VDC_V: 50V; AEC Grade: 0; AEC Category: Q200
R10 R12 R13 R53 R55 R57 R63 R64 R70-R72 R80 R82 R83 = CMP-0026822-3: RES, 0, 5%, 0.063 W, AEC-Q200 Grade 0, 0402; Manufacturer: Vishay-Dale; Power_W: 63mW; TempCo: 200 ppm/C; Value_Code: 0000; Value: 0; EIA_Code: E24; SizeX_mm: 1; SizeY_mm: 0.5; SizeZ_mm: 0.6; Value2: 0.063W; AEC Qualified: Y; VDC_V: 50V; AEC Category: Q200
R11 R17 R22 = CMP-0023343-3: RES, 0, 1%, 0.1 W, AEC-Q200 Grade 0, 0603; Manufacturer: Stackpole Electronics Inc; Power_W: 100mW; TempCo: ppm/C; U/M: EA; Value: 0; SizeX_mm: 1.6; SizeY_mm: 0.8; SizeZ_mm: 1; Value2: 0.1W; SizeArea_mm2: 1.28; AEC Qualified: Y; AEC Category: Q200
R14 R50 R97 R130 R134-R137 = CMP-0026748-1: RES, 10.0 k, 1%, 0.063 W, AEC-Q200 Grade 0, 0402; Manufacturer: KOA Speer; Power_W: 63mW; TempCo: 100 ppm/C; Value_Code: 10k0; U/M: EA; Value: 10.0k; EIA_Code: E96; Res_ohm: 10k; SizeX_mm: 1; SizeY_mm: 0.5; SizeZ_mm: 0.6; Value2: 0.063W; AEC Qualified: Y; VDC_V: 50V; AEC Grade: 0; AEC Category: Q200
R18 R21 = CMP-0022532-4: RES, 60.4 k, 1%, 0.1 W, AEC-Q200 Grade 0, 0603; Manufacturer: Vishay-Dale; Power_W: 100mW; TempCo: 100 ppm/C; Value_Code: 60k4; Value: 60.4k; EIA_Code: E96; SizeX_mm: 1.6; SizeY_mm: 0.8; SizeZ_mm: 1; Value2: 0.1W; SizeArea_mm2: 1.28; AEC Qualified: Y; VDC_V: 75V; AEC Category: Q200; AEC Grade: 0
R23 = CMP-0022138-4: RES, 1.00 M, 1%, 0.1 W, AEC-Q200 Grade 0, 0603; Manufacturer: Vishay-Dale; Power_W: 100mW; TempCo: 100 ppm/C; Value_Code: 1M00; Value: 1.00Meg; EIA_Code: E96; Res_ohm: 1M; SizeX_mm: 1.6; SizeY_mm: 0.8; SizeZ_mm: 1; Value2: 0.1W; SizeArea_mm2: 1.28; AEC Qualified: Y; VDC_V: 75V; AEC Category: Q200; AEC Grade: 0
R34-R36 R125 R131 = CMP-0025951-3: RES, 100, 1%, 0.063 W, AEC-Q200 Grade 0, 0402; Manufacturer: Vishay-Dale; Power_W: 63mW; TempCo: 100 ppm/C; Value_Code: 100R; Value: 100; EIA_Code: E96; SizeX_mm: 1; SizeY_mm: 0.5; SizeZ_mm: 0.6; Value2: 0.063W; AEC Qualified: Y; VDC_V: 50V; AEC Category: Q200; AEC Grade: 0
R87 R96 = CMP-0026071-3: RES, 1.00 k, 1%, 0.063 W, AEC-Q200 Grade 0, 0402; Manufacturer: Vishay-Dale; Power_W: 63mW; TempCo: 100 ppm/C; Value_Code: 1k00; Value: 1.00k; EIA_Code: E96; Res_ohm: 1k; SizeX_mm: 1; SizeY_mm: 0.5; SizeZ_mm: 0.6; Value2: 0.063W; AEC Qualified: Y; VDC_V: 50V; AEC Category: Q200; AEC Grade: 0
R91 R95 = CMP-0026750-1: RES, 3.30 k, 1%, 0.063 W, AEC-Q200 Grade 0, 0402; Manufacturer: KOA Speer; Power_W: 63mW; TempCo: 100 ppm/C; Value_Code: 3k30; U/M: EA; Value: 3.30k; Res_ohm: 3.3k; SizeX_mm: 1; SizeY_mm: 0.5; SizeZ_mm: 0.6; Value2: 0.063W; AEC Qualified: Y; VDC_V: 50V; AEC Grade: 0; AEC Category: Q200
R92 = CMP-0026337-2: RES, 3.65 k, 1%, 0.063 W, AEC-Q200 Grade 0, 0402; Manufacturer: Vishay-Dale; Power_W: 63mW; TempCo: 100 ppm/C; Value_Code: 3k65; Value: 3.65k; EIA_Code: E96; SizeX_mm: 1; SizeY_mm: 0.5; SizeZ_mm: 0.6; Value2: 0.063W; AEC Qualified: Y; VDC_V: 50V; AEC Category: Q200; AEC Grade: 0
R93 = CMP-0078244-2: RES, 30.0 k, 1%, 0.063 W, AEC-Q200 Grade 0, 0402; Manufacturer: Vishay-Dale; Power_W: 63mW; Green_Lifecycle: Active; TempCo: 100 ppm/C; Value_Code: 30k0; Green_REACh: Passed; Value: 30.0k; Res_ohm: 30k; SizeX_mm: 1; SizeY_mm: 0.5; SizeZ_mm: 0.6; Value2: 0.063W; AEC Qualified: Y; VDC_V: 50V; AEC Grade: 0; AEC Category: Q200
R94 = CMP-0025950-3: RES, 100 k, 1%, 0.063 W, AEC-Q200 Grade 0, 0402; Manufacturer: Vishay-Dale; Power_W: 63mW; TempCo: 100 ppm/C; Value: 100k; EIA_Code: E96; SizeX_mm: 1; SizeY_mm: 0.5; SizeZ_mm: 0.6; Value2: 0.063W; AEC Qualified: Y; VDC_V: 50V; AEC Category: Q200; AEC Grade: 0
TP3 TP4 = CMP-0003719-1: Testpoint; Manufacturer: Texas Instruments; CompType: Pad
U1 U2 = CMP-0860825-3: 5-V, Bidirectional 8:1, 1-Channel and 4:1, 2-Channel Multiplexers with Current Injection Control, DYY0016A (SOT-23-THIN-16); Alternate Manufacturer: Texas Instruments; AEC Qualified: N; CompType: IC; AEC Category: Q200; SizeY_mm: 4.2; SizeZ_mm: 1.1; SizeArea_mm2: 13.692; SizeAreaWB_mm2: 22.152; SizeX_mm: 3.26
U3 = CMP-0089855-1: Low-Power Fault Protected CAN FD Transceiver with INH and WAKE; Manufacturer: Texas Instruments; Max Supply Voltage: 28V; Standoff Height: 0mm; Min Supply Voltage: 1.7V; AEC Grade: Grade 1; SizeZ_mm: 1.1mm; TJmax_C: +165°C; AEC Qualified: Yes
U4 = CMP-0051573-2: Automotive Catalog Single 2-Input Positive-AND Gate, DBV0005A (SOT-23-5); Generic Part Number: SN74AHC1G08-Q1; Manufacturer: Texas Instruments; Output Drive (IOL/IOH)(Max)(mA): 50/-50; Output Type: CMOS; Logic: True; Bits(#): 1; Schmitt Trigger: No; VCC(Max)(V): 5.5; Gate Type: AND; VCC(Min)(V): 2; Voltage(Nom)(V): 3.3,5; tpd @ Nom Voltage(Max)(ns): 12.3,7.9; F @ Nom Voltage(Max)(Mhz): 75; ICC @ Nom Voltage(Max)(mA): 0.01; AEC Category: Q200; AEC Qualified: Y; CompType: IC; SizeAreaWB_mm2: 14.82; SizeArea_mm2: 8.12; SizeX_mm: 2.8; SizeY_mm: 2.9; SizeZ_mm: 1.45
U14 = CMP-0054481-1: Automotive Catalog Quadruple 2-Input Positive-AND Gate, PW0014A, LARGE T&R; Manufacturer: Texas Instruments; Generic Part Number: SN74AHC08Q-Q1; Output Drive (IOL/IOH)(Max)(mA): -50/50; F @ Nom Voltage(Max)(Mhz): 110; Schmitt Trigger: No; tpd @ Nom Voltage(Max)(ns): 14,9; VCC(Min)(V): 2; VCC(Max)(V): 5.5; Bits(#): 4; Technology Family: AHC; Input Type: CMOS; ICC @ Nom Voltage(Max)(mA): 0.02; Voltage(Nom)(V): 3.3,5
